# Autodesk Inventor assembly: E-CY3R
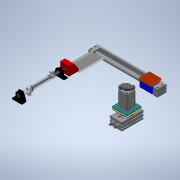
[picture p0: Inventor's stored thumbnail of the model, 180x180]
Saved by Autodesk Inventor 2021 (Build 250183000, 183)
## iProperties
Created: 2021-01
Part Number: E-CY3R
Material: Genérico
Document SubType Name: Assembly
Designer: ATOUZA
Author: ATOUZA
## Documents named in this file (10)
- D:\01 Paralaia\Grupos de Traballo\GT Maquetas\CAD 3D\E_Alimentación\Estación Alimentación.iam
- D:\01 Paralaia\Grupos de Traballo\GT Maquetas\CAD 3D\E_Alimentación\SMC_JP_CY3R15200M9B000\CY3R15-200-M9B(0_0_0).iam
- D:\01 Paralaia\Grupos de Traballo\GT Maquetas\CAD 3D\E_Alimentación\SoportePieza-CY3R.ipt
- D:\01 Paralaia\Grupos de Traballo\GT Maquetas\CAD 3D\E_Alimentación\PuenteTranporte.ipt
- D:\01 Paralaia\Grupos de Traballo\GT Maquetas\CAD 3D\E_Alimentación\SMC_JP_CD85N16100MBM9B000\CD85N16-100M-B-M9B(0__0_0).iam
- D:\01 Paralaia\Grupos de Traballo\GT Maquetas\CAD 3D\E_Alimentación\EmpujadorCilindro.ipt
- D:\01 Paralaia\Grupos de Traballo\GT Maquetas\CAD 3D\E_Alimentación\SMC_JP_MSQXB10AM9B0\MSQXB10A-M9B(0).iam
- D:\01 Paralaia\Grupos de Traballo\GT Maquetas\CAD 3D\E_Alimentación\SMC_JP_CDQMB2530M9B000\CDQMB25-30-M9B(0_0_0).iam
- D:\01 Paralaia\Grupos de Traballo\GT Maquetas\CAD 3D\E_Alimentación\Placa cilindro rotatorio.ipt
- D:\01 Paralaia\Grupos de Traballo\GT Maquetas\CAD 3D\E_Alimentación\Placa cilindro elevador.ipt
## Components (9 placed, 9 different names)
1. CY3R15-200-M9B(0_0_0):1 [sub-assembly] — Insertar:1, Insertar:2
2. SoportePieza-CY3R:1 — Insertar:1, Insertar:2
3. PuenteTranporte:1 — Coincidencia:1, Coincidencia:2, Coincidencia:3
4. CD85N16-100M-B-M9B(0__0_0):1 [sub-assembly] — Ángulo:1, Coincidencia:3, Insertar:3
5. EmpujadorCilindro:1 — Ángulo:1, Coincidencia:1, Coincidencia:2, Insertar:3
6. MSQXB10A-M9B(0):1 [sub-assembly] — Coincidencia:7, Coincidencia:8, Coincidencia:9
7. CDQMB25-30-M9B(0_0_0):1 [sub-assembly] — Nivelación:3
8. Placa cilindro rotatorio:1 — Coincidencia:4, Coincidencia:5, Coincidencia:6, Coincidencia:7, Coincidencia:8, Coincidencia:9
9. Placa cilindro elevador:1 — Nivelación:3, Coincidencia:4, Coincidencia:5, Coincidencia:6
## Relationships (14: Mate 9, Insert 3, Angle 1, Flush 1)
- Insertar:1: CY3R15-200-M9B(0_0_0):1 ↔ SoportePieza-CY3R:1
- Insertar:2: CY3R15-200-M9B(0_0_0):1 ↔ SoportePieza-CY3R:1
- Ángulo:1 [Angle]: CD85N16-100M-B-M9B(0__0_0):1 ↔ EmpujadorCilindro:1
- Coincidencia:1 [Mate]: PuenteTranporte:1 ↔ EmpujadorCilindro:1
- Coincidencia:2 [Mate]: PuenteTranporte:1 ↔ EmpujadorCilindro:1
- Coincidencia:3 [Mate]: PuenteTranporte:1 ↔ CD85N16-100M-B-M9B(0__0_0):1
- Insertar:3: CD85N16-100M-B-M9B(0__0_0):1 ↔ EmpujadorCilindro:1
- Nivelación:3 [Flush]: CDQMB25-30-M9B(0_0_0):1 ↔ Placa cilindro elevador:1
- Coincidencia:4 [Mate]: Placa cilindro rotatorio:1 ↔ Placa cilindro elevador:1
- Coincidencia:5 [Mate]: Placa cilindro rotatorio:1 ↔ Placa cilindro elevador:1
- Coincidencia:6 [Mate]: Placa cilindro rotatorio:1 ↔ Placa cilindro elevador:1
- Coincidencia:7 [Mate]: MSQXB10A-M9B(0):1 ↔ Placa cilindro rotatorio:1
- Coincidencia:8 [Mate]: MSQXB10A-M9B(0):1 ↔ Placa cilindro rotatorio:1
- Coincidencia:9 [Mate]: MSQXB10A-M9B(0):1 ↔ Placa cilindro rotatorio:1
